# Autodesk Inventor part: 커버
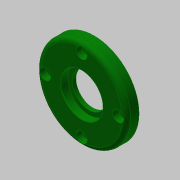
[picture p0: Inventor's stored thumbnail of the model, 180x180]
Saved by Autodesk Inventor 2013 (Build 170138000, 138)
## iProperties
Created: 2019-09
Part Number: 커버
Material: 일반
Document SubType Name: Modeling
Designer: mduedu
Density: 1 g/cm^3
Mass: 22.4538 g
Surface Area: 89.588 cm^2
Volume: 22.4538 cm^3
Author: mduedu
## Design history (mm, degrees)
sketch "스케치1"
  geometry: C1 r 32 at (0, 0); 1 further point
  constraints: 1 centre point, 1 coincident
  dimensions: "d0" = 64 diameter of C1
extrude "돌출1" new body sketch "스케치1" distance "d1" = 9; taper "d2" = 0 deg
sketch "스케치2"
  geometry: C1 r 21 at (0, 0); 1 further point
  constraints: 1 centre point, 1 coincident
  dimensions: "d3" = 42 diameter of C1
extrude "돌출2" join sketch "스케치2" distance "d4" = 3; taper "d5" = 0 deg
hole "구멍1" diameter "d8" = 24; stored, may be unused: countersink angle "d12" = 90 deg, drill point angle "d14" = 118 deg; dims "d6" = 10, "d7" = 10, "d9" = 6, "d10" = 30, "d11" = 5.2, "d13" = 8
hole "구멍2" diameter "d17" = 37; stored, may be unused: countersink angle "d21" = 90 deg, drill point angle "d23" = 0 deg; dims "d15" = 10, "d16" = 10, "d18" = 6, "d19" = 30, "d20" = 5.2, "d22" = 4
fillet "모깎기1" dims "d24" = 3
fillet "모깎기2" dims "d25" = 3
chamfer "모따기1" distance "d27" = 0.5; stored, may be unused: second distance "d28" = 2, angle "d29" = 30 deg
chamfer "모따기2" distance "d30" = 1; stored, may be unused: second distance "d31" = 2, angle "d32" = 30 deg
sketch "스케치3" dims "d33" = 52
  geometry: 3 further points
  constraints: 2 vertical alignment, 1 coincident, 2 other
hole "구멍3" sketch "스케치3" at (0, 26) diameter "d34" = 4.5; stored, may be unused: countersink angle "d38" = 90 deg, drill point angle "d40" = 0 deg; dims "d35" = 6, "d36" = 8, "d37" = 4.4, "d39" = 4
node "솔리드1"
pattern_circular "원형 패턴1" dims angle "d42" = 360 deg
